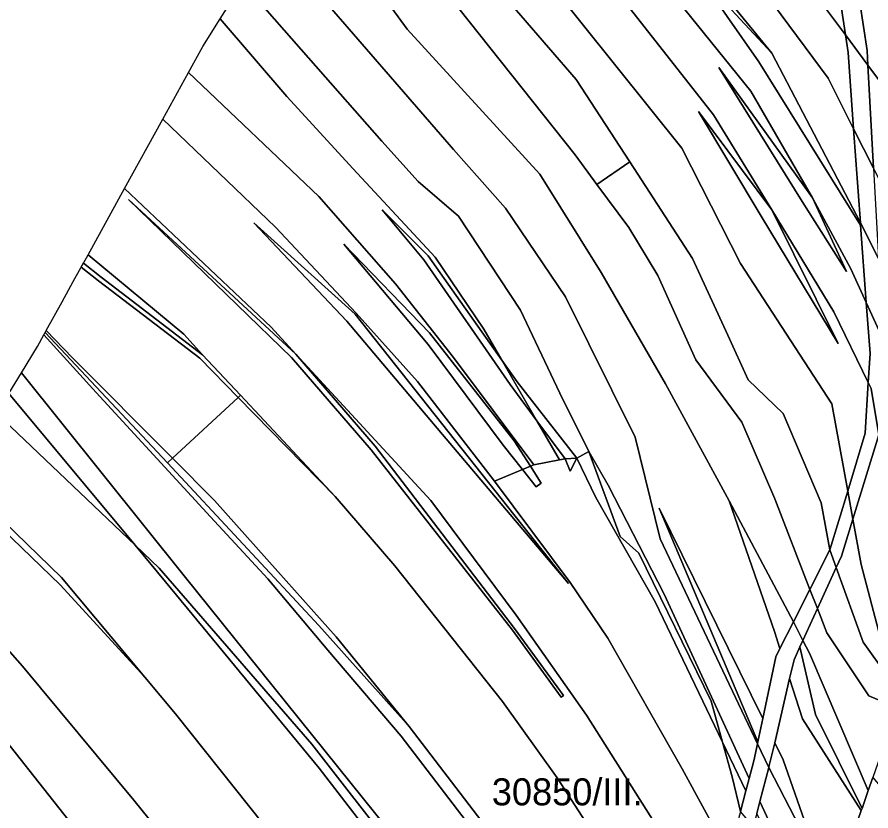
# Model space of a CAD drawing. Extents: x -537068 to -534056, y -1176840 to -1172401.
# Drawn here: x -536900.9 to -536743, y -1173632.2 to -1173485.4 of the extents above; entities that cross this region are included whole.
import ezdxf

# ---------------------------------------------------------------- set-up
doc = ezdxf.new("R2010")
doc.units = 0
for name, color, linetype in [('95580013', 7, 'Continuous'), ('95610013', 7, 'Continuous'), ('95640013', 7, 'Continuous'), ('95660013', 7, 'Continuous')]:
    doc.layers.add(name, color=color, linetype=linetype)

msp = doc.modelspace()

# ---------------------------------------------------------------- linework, layer by layer
at = {"layer": '95580013'}
for points in [[(-536909.76, -1173572.5), (-536892.69, -1173589.02), (-536877.28, -1173607.47), (-536892.94, -1173590.39), (-536912.55, -1173571.48), (-536911.89, -1173570.39)], [(-536899.91, -1173605.44), (-536919.66, -1173583.1), (-536912.55, -1173571.48), (-536892.94, -1173590.39), (-536877.28, -1173607.47), (-536871.63, -1173614.24), (-536844.37, -1173648.47), (-536828.27, -1173668.04), (-536795.97, -1173719.79), (-536807.52, -1173720.67), (-536814.12, -1173716.89), (-536816.82, -1173712.14), (-536842.19, -1173678.03), (-536858.93, -1173655.49), (-536879.33, -1173630.2)], [(-536814.12, -1173716.89), (-536816.89, -1173715.3), (-536830.12, -1173718.3), (-536841.16, -1173700.73), (-536860.73, -1173673.09), (-536890.44, -1173635.15), (-536907.81, -1173613.19), (-536926.19, -1173593.77), (-536919.66, -1173583.1), (-536899.91, -1173605.44), (-536879.33, -1173630.2), (-536858.93, -1173655.49), (-536842.19, -1173678.03), (-536816.82, -1173712.14)], [(-536926.19, -1173593.77), (-536907.81, -1173613.19), (-536890.44, -1173635.15), (-536860.73, -1173673.09), (-536841.16, -1173700.73), (-536830.12, -1173718.3), (-536837.38, -1173719.95), (-536839.52, -1173717.94), (-536846.34, -1173707.23), (-536852.43, -1173705.78), (-536875.56, -1173672.15), (-536912.59, -1173624), (-536932.52, -1173602.93), (-536927.81, -1173596.41)]]:
    msp.add_lwpolyline(points, close=True, dxfattribs=at)
at = {"layer": '95610013'}
for points in [[(-536761.05, -1173483.01), (-536780.9, -1173453.47), (-536811.63, -1173396.67), (-536807.24, -1173387.92), (-536805.86, -1173384.88), (-536779.6, -1173438), (-536770.95, -1173450.55), (-536760.36, -1173466.88), (-536775.8, -1173449.45), (-536784.13, -1173435.99), (-536778.05, -1173451.43), (-536761.41, -1173470.36), (-536755.8, -1173477.27), (-536752.34, -1173482.48), (-536747.73, -1173488.68), (-536747.24, -1173491.91), (-536746.21, -1173506.04), (-536750.93, -1173496.66)], [(-536810.37, -1173417.23), (-536816.78, -1173406.94), (-536811.63, -1173396.67), (-536780.9, -1173453.47), (-536761.05, -1173483.01), (-536750.93, -1173496.66), (-536746.21, -1173506.04), (-536744.94, -1173523.42), (-536761.35, -1173492.04), (-536768.87, -1173482.83), (-536785.92, -1173460.58), (-536792.86, -1173450.46)], [(-536792.86, -1173450.46), (-536785.92, -1173460.58), (-536768.87, -1173482.83), (-536761.35, -1173492.04), (-536775.44, -1173476.8), (-536763.71, -1173493.62), (-536744.91, -1173523.88), (-536743.87, -1173538.18), (-536746.73, -1173531.93), (-536753.8, -1173518.77), (-536765.21, -1173499.07), (-536780.04, -1173480.7), (-536795.33, -1173460.01), (-536821.63, -1173416.6), (-536816.78, -1173406.94), (-536810.37, -1173417.23)], [(-536771.14, -1173494.71), (-536755.71, -1173519.46), (-536747.53, -1173532.44), (-536753.8, -1173518.77), (-536746.73, -1173531.93), (-536743.87, -1173538.18), (-536743.18, -1173547.58), (-536743.51, -1173552.94), (-536749.9, -1173539.86), (-536761.32, -1173521.03), (-536772.15, -1173503.44), (-536803.76, -1173463.15), (-536826.22, -1173425.75), (-536821.63, -1173416.6), (-536795.33, -1173460.01), (-536780.04, -1173480.7), (-536765.21, -1173499.07), (-536753.8, -1173518.77)], [(-536803.76, -1173463.15), (-536772.15, -1173503.44), (-536761.32, -1173521.03), (-536774.9, -1173502.85), (-536763.32, -1173522.18), (-536749.07, -1173545.72), (-536761.32, -1173521.03), (-536749.9, -1173539.86), (-536743.51, -1173552.94), (-536744.08, -1173562.31), (-536747.31, -1173573.02), (-536750.25, -1173556.87), (-536767.15, -1173530.97), (-536777.98, -1173509.6), (-536808.59, -1173471.31), (-536818.95, -1173454.8), (-536832.27, -1173436.41), (-536830.84, -1173434.15), (-536828.87, -1173431.02), (-536826.22, -1173425.75)], [(-536769.46, -1173544.17), (-536775.99, -1173530.01), (-536787.61, -1173512.13), (-536797.5, -1173496.91), (-536817.98, -1173473.16), (-536838.18, -1173445.78), (-536832.27, -1173436.41), (-536818.95, -1173454.8), (-536808.59, -1173471.31), (-536777.98, -1173509.6), (-536767.15, -1173530.97), (-536750.25, -1173556.87), (-536747.31, -1173573.02), (-536750.59, -1173583.92), (-536752.24, -1173575.21), (-536759.21, -1173558.71), (-536765.71, -1173552.44)], [(-536842.65, -1173452.86), (-536838.18, -1173445.78), (-536817.98, -1173473.16), (-536797.5, -1173496.91), (-536787.61, -1173512.13), (-536793.68, -1173516.31), (-536797.73, -1173510.87), (-536823.3, -1173478.63)], [(-536747.56, -1173448.93), (-536742.46, -1173458.57), (-536738.12, -1173466.77), (-536733.58, -1173475.36), (-536729.28, -1173483.49), (-536723.75, -1173493.94), (-536720.72, -1173504.2), (-536718.46, -1173515.75), (-536717.9, -1173518.59), (-536718.65, -1173532.09), (-536719.77, -1173542.71), (-536735.42, -1173506.82), (-536740.51, -1173498.39), (-536743.58, -1173494.26), (-536743.73, -1173491.55), (-536748.44, -1173460.44), (-536752.87, -1173448.15), (-536748.29, -1173447.54)], [(-536752.34, -1173482.48), (-536754.26, -1173474.99), (-536760.36, -1173466.88), (-536770.95, -1173450.55), (-536766.84, -1173450), (-536761.69, -1173454.38), (-536755.51, -1173450.29), (-536751.91, -1173461.06), (-536747.73, -1173488.68)], [(-536797.73, -1173510.87), (-536793.68, -1173516.31), (-536787.76, -1173524.26), (-536782.39, -1173533.16), (-536775.39, -1173548.78), (-536766.86, -1173560.28), (-536760.76, -1173574.45), (-536754.28, -1173591.21), (-536757.32, -1173597.22), (-536769.22, -1173574.86), (-536781.02, -1173553.2), (-536792.88, -1173532.59), (-536804.22, -1173514.45), (-536828.79, -1173487.62), (-536847.94, -1173461.26), (-536842.65, -1173452.86), (-536823.3, -1173478.63)], [(-536782.16, -1173576.18), (-536763.91, -1173619.41), (-536763.98, -1173619.76), (-536782.01, -1173581.89), (-536786.6, -1173563.06), (-536799.48, -1173537.12), (-536810.59, -1173520.72), (-536820.22, -1173509.85), (-536853.98, -1173470.84), (-536847.94, -1173461.26), (-536828.79, -1173487.62), (-536804.22, -1173514.45), (-536792.88, -1173532.59), (-536781.02, -1173553.2), (-536769.22, -1173574.86), (-536760.86, -1173598.99), (-536759.83, -1173602.17), (-536760.6, -1173603.69), (-536763, -1173615.11)], [(-536820.22, -1173509.85), (-536810.59, -1173520.72), (-536799.48, -1173537.12), (-536786.6, -1173563.06), (-536782.01, -1173581.89), (-536763.98, -1173619.76), (-536764.65, -1173622.95), (-536765.52, -1173626.2), (-536781.27, -1173592.11), (-536791.62, -1173571.97), (-536795.21, -1173565.74), (-536800.53, -1173554.91), (-536807.8, -1173539.55), (-536819.28, -1173522.16), (-536826.77, -1173515.8), (-536833.45, -1173508.29), (-536842.5, -1173498.05), (-536859.16, -1173479.05), (-536853.98, -1173470.84)], [(-536819.28, -1173522.16), (-536807.8, -1173539.55), (-536800.53, -1173554.91), (-536795.21, -1173565.74), (-536797.41, -1173566.97), (-536808.45, -1173552.82), (-536811.25, -1173548.85), (-536814.6, -1173543.06), (-536823.57, -1173529.8), (-536838.78, -1173513.42), (-536851.05, -1173500.04), (-536863.34, -1173485.69), (-536859.16, -1173479.05), (-536842.5, -1173498.05), (-536833.45, -1173508.29), (-536826.77, -1173515.8)], [(-536845.14, -1173518.58), (-536869.22, -1173495.62), (-536866.57, -1173490.8), (-536863.34, -1173485.69), (-536851.05, -1173500.04), (-536838.78, -1173513.42), (-536823.57, -1173529.8), (-536814.6, -1173543.06), (-536811.25, -1173548.85), (-536824.87, -1173529.52), (-536833.4, -1173521.03), (-536825.72, -1173530.27), (-536809.75, -1173553.33), (-536804.77, -1173560.04), (-536800.59, -1173567.27), (-536805.35, -1173568.17), (-536820.23, -1173548.34), (-536830.91, -1173534.68)], [(-536740.51, -1173498.39), (-536735.42, -1173506.82), (-536719.77, -1173542.71), (-536720.51, -1173549.66), (-536721.14, -1173555.6), (-536717.02, -1173571.09), (-536729.12, -1173541.2), (-536736.38, -1173525.4), (-536740.28, -1173517.82), (-536742.54, -1173513.34), (-536743.58, -1173494.26)], [(-536811.03, -1173564.57), (-536807.45, -1173569.04), (-536812.6, -1173571.17), (-536826.84, -1173552.78), (-536838.23, -1173540.11), (-536853.11, -1173524.21), (-536873.99, -1173504.27), (-536869.22, -1173495.62), (-536845.14, -1173518.58), (-536830.91, -1173534.68), (-536820.23, -1173548.34), (-536805.35, -1173568.17), (-536805.98, -1173568.43), (-536809.01, -1173563.71), (-536824.62, -1173543.79), (-536840.46, -1173527.36), (-536824.89, -1173545.91)], [(-536853.11, -1173524.21), (-536838.23, -1173540.11), (-536826.84, -1173552.78), (-536812.6, -1173571.17), (-536798.62, -1173589.96), (-536791.69, -1173600.24), (-536777.91, -1173624.39), (-536769.28, -1173640.22), (-536772.2, -1173651.13), (-536772.3, -1173655.41), (-536773.52, -1173653.21), (-536781.92, -1173636.14), (-536795.62, -1173614.47), (-536808.64, -1173595.99), (-536824.42, -1173574.76), (-536849.38, -1173547.7), (-536853.93, -1173542.71), (-536881.06, -1173517.1), (-536873.99, -1173504.27)], [(-536782.39, -1173533.16), (-536787.76, -1173524.26), (-536793.68, -1173516.31), (-536787.61, -1173512.13), (-536775.99, -1173530.01), (-536769.46, -1173544.17), (-536765.71, -1173552.44), (-536759.21, -1173558.71), (-536752.24, -1173575.21), (-536750.59, -1173583.92), (-536754.28, -1173591.21), (-536760.76, -1173574.45), (-536766.86, -1173560.28), (-536775.39, -1173548.78)], [(-536857.16, -1173523.45), (-536839.92, -1173541.6), (-536825.96, -1173558.2), (-536798.94, -1173590.14), (-536838.39, -1173540.31)], [(-536866.61, -1173547.82), (-536885.35, -1173533.48), (-536888.66, -1173530.9), (-536887.8, -1173529.34), (-536870.08, -1173543.99)], [(-536889.05, -1173531.62), (-536885.84, -1173534.12), (-536867.1, -1173548.46), (-536860.01, -1173555.7), (-536872.18, -1173566.97), (-536890.66, -1173548.37), (-536895.52, -1173543.35), (-536892.58, -1173538.02), (-536890.52, -1173534.27)], [(-536817.06, -1173635.14), (-536802.7, -1173654.85), (-536782.46, -1173682.01), (-536773.34, -1173697.65), (-536773.89, -1173720.12), (-536796.82, -1173679.68), (-536870.03, -1173588.72), (-536900.13, -1173551.19), (-536897.15, -1173546.32), (-536895.96, -1173544.15), (-536886.27, -1173554.82), (-536865.13, -1173577.77), (-536854.54, -1173589.29), (-536843.42, -1173602.43), (-536829.89, -1173618.34)], [(-536902.45, -1173554.98), (-536879.11, -1173583.06), (-536904.71, -1173558.67)], [(-536864.41, -1173574.78), (-536872.18, -1173566.97), (-536860.01, -1173555.7), (-536842.07, -1173574.05), (-536831.03, -1173586.86), (-536811.15, -1173611.98), (-536801.01, -1173626.05), (-536791.93, -1173640.18), (-536804.9, -1173648.7), (-536814.96, -1173634.13), (-536828.4, -1173616.58), (-536841.91, -1173599.98), (-536852.67, -1173587.9)], [(-536828.27, -1173668.04), (-536844.37, -1173648.47), (-536871.63, -1173614.24), (-536877.28, -1173607.47), (-536892.69, -1173589.02), (-536909.76, -1173572.5), (-536911.89, -1173570.39), (-536904.71, -1173558.67), (-536879.11, -1173583.06), (-536873.49, -1173589.79), (-536845.07, -1173624.31), (-536815.72, -1173662.39), (-536800.26, -1173683.76), (-536777.6, -1173723.61), (-536775.96, -1173726.62), (-536790.16, -1173726.67), (-536796.42, -1173715.43), (-536808.99, -1173696.74)], [(-536804.77, -1173560.04), (-536799.56, -1173567.07), (-536800.59, -1173567.27)], [(-536731.71, -1173603.61), (-536735.03, -1173607.52), (-536737.15, -1173604.1), (-536741.26, -1173600.25), (-536744.83, -1173586.62), (-536746.36, -1173578.24), (-536741.57, -1173562.61), (-536736.82, -1173586.44), (-536734.35, -1173595.36), (-536730.49, -1173602.17)], [(-536791.69, -1173600.24), (-536798.62, -1173589.96), (-536812.6, -1173571.17), (-536807.45, -1173569.04), (-536804.89, -1173572.24), (-536803.98, -1173571.55), (-536805.98, -1173568.43), (-536805.35, -1173568.17), (-536800.59, -1173567.27), (-536799.56, -1173567.07), (-536798.62, -1173569.37), (-536797.41, -1173566.97), (-536793.89, -1173574.23), (-536782.91, -1173593.52), (-536770.45, -1173619.48), (-536768.65, -1173625.88), (-536767.15, -1173632.27), (-536769.28, -1173640.22), (-536777.91, -1173624.39)], [(-536737.01, -1173609.85), (-536739.94, -1173607.26), (-536744.46, -1173600.98), (-536749.42, -1173587.19), (-536748.45, -1173585.08), (-536746.36, -1173578.24), (-536744.83, -1173586.62), (-536741.26, -1173600.25), (-536737.15, -1173604.1), (-536735.03, -1173607.52)], [(-536738.16, -1173613.14), (-536743.4, -1173610.91), (-536751.16, -1173599.27), (-536752.9, -1173594.78), (-536749.42, -1173587.19), (-536744.46, -1173600.98), (-536739.94, -1173607.26), (-536737.01, -1173609.85)], [(-536755.59, -1173600.65), (-536752.9, -1173594.78), (-536751.16, -1173599.27), (-536743.4, -1173610.91), (-536738.16, -1173613.14), (-536742.65, -1173625.98), (-536743.51, -1173628.44), (-536754.38, -1173603.04)], [(-536756.13, -1173601.84), (-536755.59, -1173600.65), (-536754.38, -1173603.04), (-536743.51, -1173628.44), (-536744.66, -1173631.72), (-536753.26, -1173614.37)], [(-536755.64, -1173615.14), (-536744.8, -1173632.11), (-536747.16, -1173638.89), (-536747.13, -1173640.04), (-536747.08, -1173641.61), (-536754.89, -1173635.27), (-536759.26, -1173622.72), (-536760.81, -1173619.57), (-536758.04, -1173607.71)], [(-536770.45, -1173619.48), (-536766.13, -1173628.47), (-536767.15, -1173632.27), (-536768.65, -1173625.88)], [(-536756.55, -1173644.63), (-536759.82, -1173638.55), (-536763.55, -1173630.46), (-536761.89, -1173624.15), (-536757.1, -1173633.47), (-536752.17, -1173643.07), (-536754.89, -1173635.27), (-536747.08, -1173641.61), (-536746.39, -1173656.86), (-536753.69, -1173647.96)], [(-536747.16, -1173638.89), (-536744.8, -1173632.11), (-536744.66, -1173631.72), (-536743.51, -1173628.44), (-536742.65, -1173625.98), (-536738.62, -1173630.78), (-536738.92, -1173632.56), (-536740.35, -1173647.13), (-536747.13, -1173640.04)]]:
    msp.add_lwpolyline(points, close=True, dxfattribs=at)
msp.add_lwpolyline([(-536791.93, -1173640.18), (-536801.01, -1173626.05), (-536811.15, -1173611.98), (-536831.03, -1173586.86), (-536842.07, -1173574.05), (-536859.6, -1173555.32), (-536866.61, -1173547.82), (-536870.08, -1173543.99), (-536887.8, -1173529.34), (-536881.06, -1173517.1), (-536853.93, -1173542.71), (-536849.38, -1173547.7), (-536880.34, -1173519.11), (-536850.14, -1173548.35), (-536835.46, -1173565.4), (-536809.32, -1173598.74), (-536800.28, -1173611.15), (-536799.88, -1173610.86), (-536808.92, -1173598.45), (-536834.7, -1173564.75), (-536849.38, -1173547.7), (-536824.42, -1173574.76), (-536808.64, -1173595.99), (-536795.62, -1173614.47), (-536781.92, -1173636.14)], dxfattribs=at)
at = {"layer": '95640013'}
for points in [[(-536743.73, -1173491.55), (-536743.58, -1173494.26), (-536747.73, -1173488.68), (-536751.91, -1173461.06), (-536755.51, -1173450.29), (-536756.08, -1173448.57), (-536752.87, -1173448.15), (-536748.44, -1173460.44)], [(-536775.44, -1173476.8), (-536761.35, -1173492.04), (-536744.94, -1173523.42), (-536744.91, -1173523.88), (-536763.71, -1173493.62)], [(-536747.24, -1173491.91), (-536747.73, -1173488.68), (-536743.58, -1173494.26), (-536742.54, -1173513.34), (-536746.21, -1173506.04)], [(-536753.8, -1173518.77), (-536747.53, -1173532.44), (-536755.71, -1173519.46), (-536771.14, -1173494.71)], [(-536761.32, -1173521.03), (-536749.07, -1173545.72), (-536763.32, -1173522.18), (-536774.9, -1173502.85)], [(-536746.21, -1173506.04), (-536742.54, -1173513.34), (-536741.62, -1173530.03), (-536744.94, -1173523.42)], [(-536808.92, -1173598.45), (-536799.88, -1173610.86), (-536800.28, -1173611.15), (-536809.32, -1173598.74), (-536835.46, -1173565.4), (-536850.14, -1173548.35), (-536880.34, -1173519.11), (-536849.38, -1173547.7), (-536834.7, -1173564.75)], [(-536825.72, -1173530.27), (-536833.4, -1173521.03), (-536824.87, -1173529.52), (-536811.25, -1173548.85), (-536804.77, -1173560.04), (-536809.75, -1173553.33)], [(-536798.94, -1173590.14), (-536825.96, -1173558.2), (-536839.92, -1173541.6), (-536857.16, -1173523.45), (-536838.39, -1173540.31)], [(-536744.94, -1173523.42), (-536741.62, -1173530.03), (-536740.8, -1173544.87), (-536743.87, -1173538.18), (-536744.91, -1173523.88)], [(-536824.62, -1173543.79), (-536809.01, -1173563.71), (-536805.98, -1173568.43), (-536807.45, -1173569.04), (-536811.03, -1173564.57), (-536824.89, -1173545.91), (-536840.46, -1173527.36)], [(-536885.35, -1173533.48), (-536866.61, -1173547.82), (-536859.6, -1173555.32), (-536860.01, -1173555.7), (-536867.1, -1173548.46), (-536885.84, -1173534.12), (-536889.05, -1173531.62), (-536888.66, -1173530.9)], [(-536740.66, -1173547.43), (-536741.57, -1173562.61), (-536742.97, -1173554.04), (-536743.51, -1173552.94), (-536743.18, -1173547.58), (-536743.87, -1173538.18), (-536740.8, -1173544.87)], [(-536828.4, -1173616.58), (-536814.96, -1173634.13), (-536804.9, -1173648.7), (-536801.42, -1173653.75), (-536782.46, -1173682.01), (-536802.7, -1173654.85), (-536817.06, -1173635.14), (-536829.89, -1173618.34), (-536843.42, -1173602.43), (-536854.54, -1173589.29), (-536865.13, -1173577.77), (-536886.27, -1173554.82), (-536895.96, -1173544.15), (-536895.72, -1173543.73), (-536873.12, -1173567.84), (-536845.11, -1173597.87)], [(-536895.52, -1173543.35), (-536890.66, -1173548.37), (-536872.18, -1173566.97), (-536873.12, -1173567.84), (-536895.72, -1173543.73)], [(-536797.41, -1173566.97), (-536799.56, -1173567.07), (-536804.77, -1173560.04), (-536811.25, -1173548.85), (-536808.45, -1173552.82)], [(-536814.43, -1173660.95), (-536846.42, -1173619.82), (-536874.64, -1173587.31), (-536879.11, -1173583.06), (-536902.45, -1173554.98), (-536900.13, -1173551.19), (-536870.03, -1173588.72), (-536796.82, -1173679.68), (-536773.89, -1173720.12), (-536760.44, -1173742.57), (-536762.85, -1173744.9), (-536768.25, -1173734.85), (-536776.21, -1173720.04), (-536793.79, -1173690.29), (-536803.42, -1173675.57)], [(-536742.97, -1173554.04), (-536741.57, -1173562.61), (-536746.36, -1173578.24), (-536747.31, -1173573.02), (-536744.08, -1173562.31), (-536743.51, -1173552.94)], [(-536859.6, -1173555.32), (-536842.07, -1173574.05), (-536860.01, -1173555.7)], [(-536770.45, -1173619.48), (-536782.91, -1173593.52), (-536793.89, -1173574.23), (-536797.41, -1173566.97), (-536795.21, -1173565.74), (-536789.41, -1173581.44), (-536785.92, -1173584.54), (-536772.57, -1173611.91)], [(-536781.27, -1173592.11), (-536765.52, -1173626.2), (-536766.13, -1173628.47), (-536770.45, -1173619.48), (-536772.57, -1173611.91), (-536785.92, -1173584.54), (-536789.41, -1173581.44), (-536795.21, -1173565.74), (-536791.62, -1173571.97)], [(-536852.67, -1173587.9), (-536841.91, -1173599.98), (-536828.4, -1173616.58), (-536845.11, -1173597.87), (-536873.12, -1173567.84), (-536872.18, -1173566.97), (-536864.41, -1173574.78)], [(-536797.41, -1173566.97), (-536798.62, -1173569.37), (-536799.56, -1173567.07)], [(-536807.45, -1173569.04), (-536805.98, -1173568.43), (-536803.98, -1173571.55), (-536804.89, -1173572.24)], [(-536748.45, -1173585.08), (-536749.42, -1173587.19), (-536750.59, -1173583.92), (-536747.31, -1173573.02), (-536746.36, -1173578.24)], [(-536769.22, -1173574.86), (-536757.32, -1173597.22), (-536759.83, -1173602.17), (-536760.86, -1173598.99)], [(-536782.16, -1173576.18), (-536763, -1173615.11), (-536763.91, -1173619.41)], [(-536774.64, -1173729.06), (-536775.96, -1173726.62), (-536777.6, -1173723.61), (-536800.26, -1173683.76), (-536815.72, -1173662.39), (-536845.07, -1173624.31), (-536873.49, -1173589.79), (-536879.11, -1173583.06), (-536874.64, -1173587.31), (-536846.42, -1173619.82), (-536814.43, -1173660.95), (-536803.42, -1173675.57), (-536793.79, -1173690.29), (-536776.21, -1173720.04), (-536768.25, -1173734.85), (-536770.1, -1173735.75)], [(-536754.28, -1173591.21), (-536750.59, -1173583.92), (-536749.42, -1173587.19), (-536752.9, -1173594.78)], [(-536752.9, -1173594.78), (-536755.59, -1173600.65), (-536757.32, -1173597.22), (-536754.28, -1173591.21)], [(-536761.8, -1173623.8), (-536761.89, -1173624.15), (-536763.98, -1173619.76), (-536763.91, -1173619.41), (-536763, -1173615.11), (-536760.6, -1173603.69), (-536759.83, -1173602.17), (-536757.32, -1173597.22), (-536755.59, -1173600.65), (-536756.13, -1173601.84), (-536757.23, -1173604.24), (-536758.04, -1173607.71), (-536760.81, -1173619.57)], [(-536757.23, -1173604.24), (-536756.13, -1173601.84), (-536753.26, -1173614.37), (-536744.66, -1173631.72), (-536744.8, -1173632.11), (-536755.64, -1173615.14), (-536758.04, -1173607.71)], [(-536764.76, -1173635.05), (-536767.15, -1173632.27), (-536766.13, -1173628.47), (-536765.52, -1173626.2), (-536764.65, -1173622.95), (-536763.98, -1173619.76), (-536761.89, -1173624.15), (-536763.55, -1173630.46), (-536764.13, -1173632.64)], [(-536757.1, -1173633.47), (-536761.89, -1173624.15), (-536761.8, -1173623.8), (-536760.81, -1173619.57), (-536759.26, -1173622.72), (-536754.89, -1173635.27)], [(-536761.76, -1173637.57), (-536764.13, -1173632.64), (-536763.55, -1173630.46), (-536759.82, -1173638.55), (-536756.55, -1173644.63), (-536759.74, -1173640.91)]]:
    msp.add_lwpolyline(points, close=True, dxfattribs=at)
at = {"layer": '95660013'}
msp.add_lwpolyline([(-536902.45, -1173554.98), (-536900.13, -1173551.19), (-536897.15, -1173546.32), (-536895.96, -1173544.15), (-536895.72, -1173543.73), (-536895.52, -1173543.35), (-536892.58, -1173538.02), (-536890.52, -1173534.27), (-536889.05, -1173531.62), (-536888.66, -1173530.9), (-536887.8, -1173529.34), (-536881.06, -1173517.1), (-536873.99, -1173504.27), (-536869.22, -1173495.62), (-536866.57, -1173490.8), (-536863.34, -1173485.69), (-536859.16, -1173479.05)], dxfattribs=at)

# ---------------------------------------------------------------- texts
msp.add_text('30850/III.', height=5, rotation=0, dxfattribs=at).set_placement((-536813.12, -1173631.16))

doc.saveas('drawing.dxf')
